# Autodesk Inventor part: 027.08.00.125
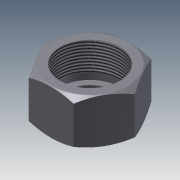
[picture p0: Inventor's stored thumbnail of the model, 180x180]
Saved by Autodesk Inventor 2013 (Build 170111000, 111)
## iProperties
Shininess: 25.0
Length Units: 11269
Angle Units: 11279
Time Units: 11290
Mass Units: 11283
Length Display Precision: 3
Angle Display Precision: 2
Created: 2001-11
Part Number: 027.08.00.125
Document SubType Name: Modeling
Designer: SOleg
Material: Steel, Mild
Density: 7.86 g/cm^3
Density: 0.0
Volumn: 0.0
Area: 0.0
PropertySet Name: Model Information
Control State: 0
Master: False
Checked Out: False
Checked Out Date: 2008-10-15
Last Check In Date: 2008-10-15
Author: SOleg
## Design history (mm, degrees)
sketch "Sketch1"
  geometry: L1 (144.878, 170.5)-(113.123, 170.5); L2 (160.758, 143.006)-(144.878, 170.5); L3 (144.88, 115.5)-(160.758, 143.006); L4 (113.13, 115.5)-(144.88, 115.5); L5 (97.248, 142.999)-(113.13, 115.5); L6 (113.123, 170.5)-(97.248, 142.999)
  constraints: 12 end point, 2 horizontal, 2 parallel, 1 other
  dimensions: "d1" = 63.51 distance of L2.start L5.start; "d3" = 55 distance of L1.start L3.start; "d5" = 55 distance of L5.start L1.start; "d7" = 63.51 distance of L3.start L1.end; "d9" = 55 distance of L3.start L5.start; "d11" = 31.75 distance of L4.start L3.start
extrude "ExtrusionBlind1" new body sketch "Sketch1" distance "d12" = 32; taper "d13" = 0 deg
node "WorkPlane1"
sketch "Sketch2"
  geometry: C1 r 17 at (-129.004, 143.001)
  constraints: 1 centre point
  dimensions: "d16" = 34 diameter of C1
extrude "ExtrusionBlind2" cut sketch "Sketch2" distance "d17" = 7; taper "d18" = 0 deg
node "WorkAxis1"
sketch "Sketch3"
  geometry: C1 r 21.5 at (0, 0)
  constraints: 1 centre point
  dimensions: "d21" = 43 diameter of C1
extrude "ExtrusionBlind3" cut sketch "Sketch3" distance "d22" = 5; taper "d23" = 0 deg
extrude "ExtrusionBlind4" cut distance "d27" = 30; taper "d28" = 0 deg
  node "Sketch4" dims "d26" = 42
sketch "Sketch5"
  geometry: L1 (0, -31.755)-(-32, -31.755); L2 (0, -4.755)-(0, -31.755); L3 (-4.619, 3.245)-(0, -4.755); L4 (-27.381, 3.245)-(-4.619, 3.245); L5 (-32, -4.755)-(-27.381, 3.245); L6 (-32, -31.755)-(-32, -4.755); L7 (-61.639, -31.755)-(29.639, -31.755); 1 further point
  constraints: 14 end point, 2 horizontal, 2 vertical
  dimensions: "d30" = 32 distance of L1.start L1.end; "d32" = 0 horizontal distance of L1.end point (-32, 0); "d34" = 150 deg angle of L6 L5; "d36" = 150 deg angle of L3 L2; "d38" = 27 distance of L2.start L1.start; "d40" = 35 vertical distance of L4.start L1.end
revolve "RevolutionAngle1" sketch "Sketch5" stored, may be unused: angle "d41" = 360 deg
thread "Thread1" dims "d42" = 10, "d43" = 0
body "Solid1"
other parameters: "d0" = 63.51 (derived), "d2" = 55 (derived), "d4" = 55 (derived), "d6" = 63.51 (derived), "d8" = 55 (derived), "d10" = 31.75 (derived), "d14" = 0, "d15" = 34 (derived), "d19" = 0, "d20" = 43 (derived), "d24" = 0, "d25" = 42 (derived), "d29" = 32 (derived), "d31" = 0 (derived), "d33" = 150 deg (derived), "d35" = 150 deg (derived), "d37" = 27 (derived), "d39" = 35 (derived)
